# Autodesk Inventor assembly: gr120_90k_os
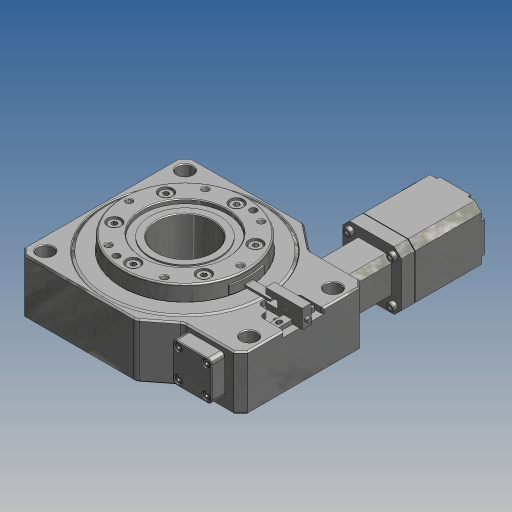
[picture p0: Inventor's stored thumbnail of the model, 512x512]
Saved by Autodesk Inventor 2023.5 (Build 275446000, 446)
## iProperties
Part Number: gr120_90k_os
Document SubType Name: Baugruppe
Designer: WH
Author: WH
Sending System: Creo  TM  5.0
NB: GR120-90K-OS
NN: GR120-OS
NBSYN: $CNSORDERNO.
LINA: GR120-90K-OS
CATALOG: GIGAGER
CNSORDERNO: GR120-90K-OS
SCS: GR120
GR: 90K
MS: OS
SUPPLIER: SAINI
ARTICLENO: GR120-90K-OS
BOMINFO: GR120-90K-OS
CREATOR: CADENAS GmbH
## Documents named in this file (6)
- C:\Users\Walter\Downloads\SWX-Gigager\gr120_90k_os\gr120_90k_os.iam
- C:\Users\Walter\Downloads\SWX-Gigager\gr120_90k_os\GR120_90K_OS_DUMMY.ipt
- C:\Users\Walter\Downloads\SWX-Gigager\gr120_90k_os\GR120_1.ipt
- C:\Users\Walter\Downloads\SWX-Gigager\gr120_90k_os\GR120_OS_2.ipt
- C:\Users\Walter\Downloads\SWX-Gigager\gr120_90k_os\GR120_3.ipt
- C:\Users\Walter\Downloads\SWX-Gigager\gr120_90k_os\GR120_4.ipt
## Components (5 placed, 5 different names)
1. GR120_90K_OS_DUMMY
2. GR120_1
3. GR120_OS_2
4. GR120_3
5. GR120_4
